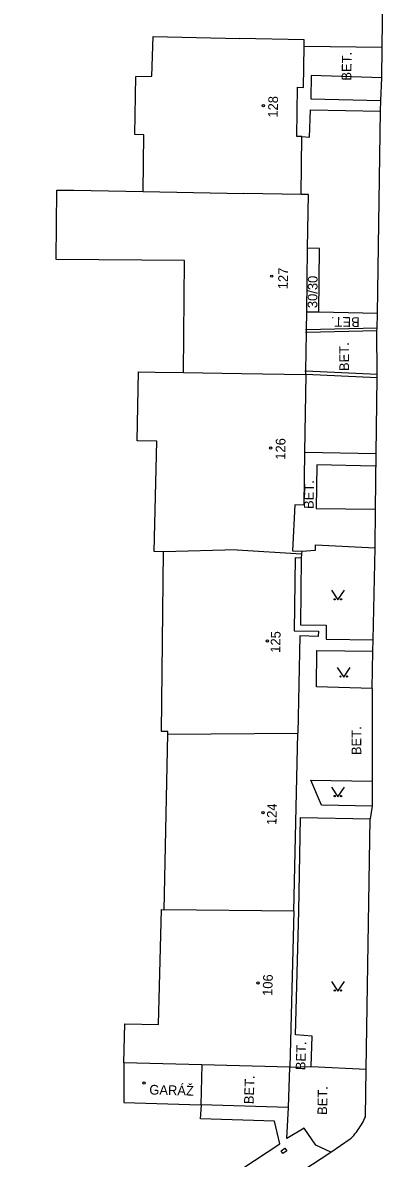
# Model space of a CAD drawing. Extents: x -544674 to -541478, y -1199076 to -1195527.
# Drawn here: x -543668.4 to -543640.2, y -1197346.5 to -1197258.5 of the extents above; entities that cross this region are included whole.
import ezdxf

# ---------------------------------------------------------------- set-up
doc = ezdxf.new("R2010")
doc.units = 0
for name, color, linetype in [('BUDOVY_MĚŘ', 7, 'Continuous'), ('BUDOVY_NEMĚŘ', 7, 'Continuous'), ('OBVOD_PILÍŘE', 7, 'Continuous'), ('POMOC_POPIS', 7, 'Continuous'), ('ROZHRANÍ_PLOCH', 7, 'Continuous'), ('ZN_BUDOV', 7, 'Continuous'), ('ZN_DOPLŇKOVÉ', 7, 'Continuous'), ('ZN_KULTUR', 7, 'Continuous'), ('Č_POPIS_ORIENT', 7, 'Continuous')]:
    doc.layers.add(name, color=color, linetype=linetype)

msp = doc.modelspace()

# ---------------------------------------------------------------- linework, layer by layer
at = {"layer": 'BUDOVY_MĚŘ'}
for points in [[(-543646.53, -1197260.38), (-543646.52, -1197259.88), (-543651.52, -1197259.78)], [(-543646.7, -1197267.37), (-543647.1, -1197267.37), (-543647.04, -1197263.55), (-543646.59, -1197263.56), (-543646.53, -1197260.38)], [(-543646.76, -1197271.85), (-543646.7, -1197267.37)], [(-543646.76, -1197271.85), (-543651.2, -1197271.79)], [(-543646.26, -1197276.03), (-543646.2, -1197271.86), (-543646.76, -1197271.85)], [(-543646.33, -1197280.97), (-543646.26, -1197276.03)], [(-543646.35, -1197282.36), (-543646.33, -1197280.97)], [(-543646.35, -1197282.56), (-543646.35, -1197282.36)], [(-543646.39, -1197285.55), (-543646.35, -1197282.56)], [(-543651.39, -1197285.73), (-543646.39, -1197285.81)], [(-543646.39, -1197285.81), (-543646.49, -1197291.84)], [(-543646.39, -1197285.81), (-543646.39, -1197285.55)], [(-543646.49, -1197291.84), (-543646.55, -1197295.93), (-543647.25, -1197295.92), (-543647.42, -1197299.46), (-543646.72, -1197299.5)], [(-543651.72, -1197299.4), (-543646.73, -1197299.7)], [(-543646.73, -1197299.7), (-543646.75, -1197300.04)], [(-543646.72, -1197299.5), (-543646.73, -1197299.7)], [(-543646.75, -1197300.04), (-543647.23, -1197300.02), (-543647.3, -1197305.66), (-543645.42, -1197305.7), (-543645.43, -1197306.1), (-543646.86, -1197306.07), (-543647.02, -1197313.6)], [(-543647.32, -1197327.39), (-543647.02, -1197313.6)], [(-543647.32, -1197327.39), (-543647.64, -1197339.49)], [(-543654.46, -1197339.31), (-543654.54, -1197342.39)], [(-543647.64, -1197339.49), (-543654.46, -1197339.31)]]:
    msp.add_lwpolyline(points, dxfattribs=at)
at = {"layer": 'BUDOVY_NEMĚŘ'}
for points in [[(-543659.03, -1197271.63), (-543658.96, -1197267.23), (-543659.67, -1197267.22), (-543659.6, -1197262.72), (-543658.35, -1197262.7), (-543658.24, -1197259.61), (-543651.52, -1197259.78)], [(-543655.88, -1197285.65), (-543655.81, -1197276.98), (-543665.76, -1197276.9), (-543665.72, -1197271.53), (-543664.4, -1197271.53), (-543659.03, -1197271.63)], [(-543659.03, -1197271.63), (-543651.2, -1197271.79)], [(-543657.43, -1197299.54), (-543658.17, -1197299.53), (-543657.97, -1197290.97), (-543659.48, -1197290.94), (-543659.37, -1197285.61), (-543658.08, -1197285.62), (-543655.88, -1197285.65)], [(-543655.88, -1197285.65), (-543651.39, -1197285.73)], [(-543657.1, -1197313.48), (-543657.61, -1197313.47), (-543657.43, -1197299.54)], [(-543651.72, -1197299.4), (-543657.43, -1197299.54)], [(-543657.4, -1197327.28), (-543657.1, -1197313.69)], [(-543657.1, -1197313.69), (-543657.1, -1197313.48)], [(-543657.1, -1197313.69), (-543647.02, -1197313.6)], [(-543660.53, -1197339.15), (-543660.45, -1197336.12), (-543657.82, -1197336.19), (-543657.6, -1197327.27), (-543657.4, -1197327.28)], [(-543647.32, -1197327.39), (-543657.4, -1197327.28)], [(-543660.53, -1197339.15), (-543660.53, -1197342.23)], [(-543654.46, -1197339.31), (-543660.53, -1197339.15)], [(-543660.53, -1197342.23), (-543654.54, -1197342.39)]]:
    msp.add_lwpolyline(points, dxfattribs=at)
at = {"layer": 'OBVOD_PILÍŘE'}
msp.add_lwpolyline([(-543648.32, -1197345.98), (-543648.02, -1197345.77), (-543647.88, -1197345.97), (-543648.03, -1197346.08), (-543648.18, -1197346.18), (-543648.32, -1197345.98)], dxfattribs=at)
at = {"layer": 'ROZHRANÍ_PLOCH'}
for points in [[(-543640.47, -1197260.46), (-543640.23, -1197241.95)], [(-543640.47, -1197260.46), (-543646.53, -1197260.38)], [(-543640.5, -1197262.83), (-543640.47, -1197260.46)], [(-543640.5, -1197262.83), (-543645.98, -1197262.64), (-543646.02, -1197264.45), (-543640.59, -1197264.57)], [(-543640.59, -1197264.57), (-543640.5, -1197262.83)], [(-543640.6, -1197265.41), (-543640.59, -1197264.57)], [(-543646.7, -1197267.37), (-543646.11, -1197267.42), (-543646.03, -1197265.29), (-543640.6, -1197265.41)], [(-543640.83, -1197281.07), (-543640.6, -1197265.41)], [(-543645.39, -1197280.99), (-543645.34, -1197276.04), (-543646.26, -1197276.03)], [(-543645.39, -1197280.99), (-543646.33, -1197280.97)], [(-543640.83, -1197281.07), (-543645.39, -1197280.99)], [(-543640.87, -1197282.23), (-543640.83, -1197281.07)], [(-543640.88, -1197282.43), (-543640.87, -1197282.23)], [(-543640.85, -1197285.8), (-543640.88, -1197282.43)], [(-543640.85, -1197286.06), (-543640.85, -1197285.8)], [(-543640.94, -1197291.93), (-543640.85, -1197286.06)], [(-543646.49, -1197291.84), (-543640.94, -1197291.93)], [(-543641, -1197296.25), (-543640.94, -1197291.93)], [(-543641.02, -1197292.92), (-543645.55, -1197292.82), (-543645.6, -1197296.18), (-543641, -1197296.25)], [(-543641.02, -1197299.23), (-543641, -1197296.25)], [(-543646.72, -1197299.5), (-543645.65, -1197299.41), (-543645.65, -1197299.01), (-543641.02, -1197299.23)], [(-543641.17, -1197306.37), (-543641.02, -1197299.23)], [(-543646.75, -1197300.04), (-543646.81, -1197305.21), (-543644.82, -1197305.23), (-543644.83, -1197306.33), (-543641.17, -1197306.37)], [(-543641.19, -1197307.24), (-543641.17, -1197306.37)], [(-543641.24, -1197310.14), (-543645.58, -1197310.02), (-543645.54, -1197307.19), (-543641.19, -1197307.24)], [(-543641.24, -1197310.14), (-543641.19, -1197307.24)], [(-543641.24, -1197310.14), (-543641.25, -1197317.32)], [(-543641.25, -1197319.25), (-543645.18, -1197319.18), (-543646.01, -1197317.24), (-543641.25, -1197317.32)], [(-543641.25, -1197317.32), (-543641.25, -1197319.25)], [(-543641.25, -1197319.25), (-543641.4, -1197320.25)], [(-543645.98, -1197339.44), (-543645.9, -1197337.07), (-543647.21, -1197336.99), (-543646.95, -1197327.4), (-543646.8, -1197320.13), (-543641.4, -1197320.25)], [(-543641.72, -1197339.64), (-543641.4, -1197320.25)], [(-543647.75, -1197342.6), (-543647.64, -1197339.49)], [(-543647.64, -1197339.49), (-543645.98, -1197339.44)], [(-543645.98, -1197339.44), (-543641.72, -1197339.64)], [(-543644.47, -1197346.06), (-543642.95, -1197345.05), (-543642.88, -1197344.98), (-543642.78, -1197344.88), (-543642.68, -1197344.77), (-543642.59, -1197344.66), (-543642.5, -1197344.55), (-543642.41, -1197344.44), (-543642.33, -1197344.32), (-543642.25, -1197344.21), (-543642.17, -1197344.09), (-543642.1, -1197343.97), (-543642.03, -1197343.84), (-543641.96, -1197343.72), (-543641.9, -1197343.59), (-543641.84, -1197343.46), (-543641.78, -1197343.33), (-543641.72, -1197339.64)], [(-543647.75, -1197342.6), (-543654.54, -1197342.39)], [(-543647.86, -1197345), (-543647.75, -1197342.6)], [(-543645.62, -1197345.52), (-543646.52, -1197344.22), (-543647.86, -1197345)], [(-543644.47, -1197346.06), (-543645.62, -1197345.52)], [(-543668.37, -1197361.71), (-543644.47, -1197346.06)]]:
    msp.add_lwpolyline(points, dxfattribs=at)
at = {"layer": 'ZN_BUDOV'}
for centre in [(-543649.69, -1197264.97), (-543649.04, -1197278.19), (-543649.13, -1197291.51), (-543649.38, -1197306.45), (-543649.73, -1197319.77), (-543650.11, -1197332.96), (-543658.95, -1197340.72)]:
    msp.add_circle(centre, 0.0875, dxfattribs=at)
at = {"layer": 'ZN_DOPLŇKOVÉ'}
for points in [[(-543646.35, -1197282.36), (-543646.43, -1197282.36)], [(-543640.87, -1197282.23), (-543646.35, -1197282.36)], [(-543646.35, -1197282.56), (-543646.43, -1197282.56)], [(-543640.88, -1197282.43), (-543646.35, -1197282.56)], [(-543646.39, -1197285.55), (-543646.48, -1197285.55)], [(-543640.85, -1197285.8), (-543646.39, -1197285.55)], [(-543640.85, -1197286.06), (-543646.39, -1197285.81)], [(-543663.94, -1197351), (-543663.74, -1197354.26), (-543663.58, -1197354.97), (-543663.23, -1197355.15), (-543648.41, -1197345.42), (-543648.83, -1197343.66), (-543654.56, -1197343.5), (-543654.49, -1197342.43)]]:
    msp.add_lwpolyline(points, dxfattribs=at)
at = {"layer": 'ZN_KULTUR'}
for points in [[(-543644.41, -1197302.53), (-543643.91, -1197303.28), (-543643.41, -1197302.53)], [(-543643.96, -1197308.51), (-543643.46, -1197309.26), (-543642.96, -1197308.51)], [(-543644.41, -1197317.78), (-543643.91, -1197318.53), (-543643.41, -1197317.78)], [(-543644.41, -1197332.84), (-543643.91, -1197333.59), (-543643.41, -1197332.84)]]:
    msp.add_lwpolyline(points, dxfattribs=at)
for centre in [(-543644.16, -1197303.23), (-543643.66, -1197303.23), (-543643.71, -1197309.21), (-543643.21, -1197309.21), (-543644.16, -1197318.48), (-543643.66, -1197318.48), (-543644.16, -1197333.54), (-543643.66, -1197333.54)]:
    msp.add_circle(centre, 0.05, dxfattribs=at)

# ---------------------------------------------------------------- texts
at = {"layer": 'POMOC_POPIS'}
for s, rotation, p in [('BET.', 89.26001, (-543642.87, -1197263.04)), ('30/30', 89.41998, (-543645.51, -1197280.67)), ('BET.', 178.99998, (-543642.21, -1197281.38)), ('BET.', 90.51003, (-543643.04, -1197285.54)), ('BET.', 89.09998, (-543645.8, -1197296.23)), ('BET.', 89.93999, (-543642.1, -1197315.3)), ('BET.', 88.06997, (-543646.44, -1197339.73)), ('BET.', 87.96999, (-543650.45, -1197342.36)), ('GARÁŽ', 358.49998, (-543658.55, -1197341.6)), ('BET.', 89.05002, (-543644.75, -1197343.19))]:
    msp.add_text(s, height=0.75, rotation=rotation, dxfattribs=at).set_placement(p)
at = {"layer": 'Č_POPIS_ORIENT'}
for s, rotation, p in [('128', 89.09998, (-543648.58, -1197265.91)), ('127', 89.22001, (-543647.8, -1197279.21)), ('126', 89.09001, (-543648, -1197292.42)), ('125', 88.77998, (-543648.39, -1197307.38)), ('124', 88.75002, (-543648.68, -1197320.73)), ('106', 88.49001, (-543649, -1197333.97))]:
    msp.add_text(s, height=0.75, rotation=rotation, dxfattribs=at).set_placement(p)

doc.saveas('drawing.dxf')
